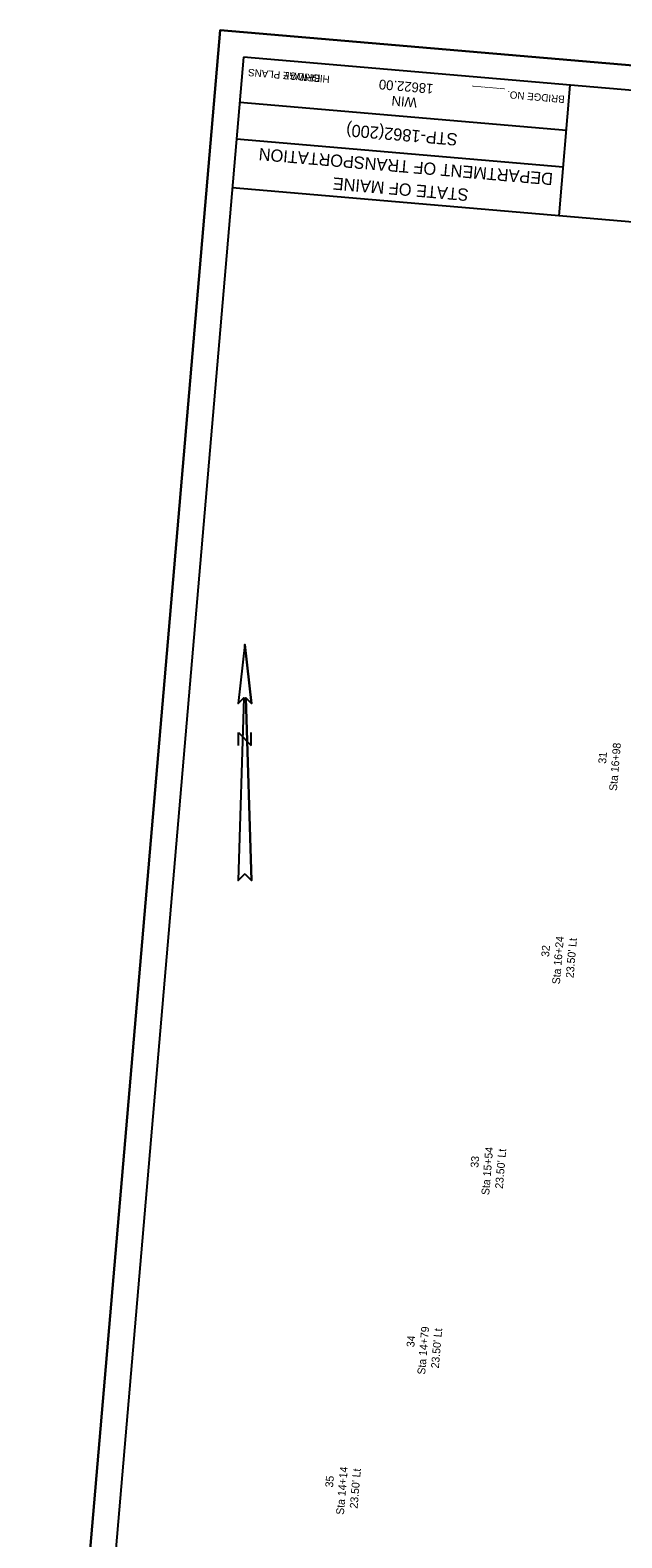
# Model space of a CAD drawing. Extents: x 1137099 to 1137719, y 529062 to 529956.
# Drawn here: x 1137099 to 1137324, y 529381 to 529956 of the extents above; entities that cross this region are included whole.
import ezdxf

# ---------------------------------------------------------------- set-up
doc = ezdxf.new("R2010")
doc.units = 0
for name, color, linetype in [('ANNOTATION', 7, 'Continuous'), ('BORDER', 7, 'Continuous'), ('BRIDGE_TITLE', 7, 'Continuous'), ('D_Lighting_Text', 7, 'Continuous'), ('H_V CONTROLS', 7, 'Continuous'), ('HIGHWAY_TITLE', 7, 'Continuous'), ('PLOT BOUNDARY', 7, 'Continuous')]:
    doc.layers.add(name, color=color, linetype=linetype)

msp = doc.modelspace()

# ---------------------------------------------------------------- linework, layer by layer
at = {"layer": 'ANNOTATION'}
msp.add_lwpolyline([(1137098.65, 529108.8), (1137171.14, 529955.71), (1137719.13, 529908.81), (1137646.65, 529061.9)], close=True, dxfattribs=at)
at = {"layer": 'BORDER'}
for p, q in [((1137179.99, 529945.38), (1137111.77, 529148.3)), ((1137703.07, 529900.61), (1137179.98, 529945.38)), ((1137300.3, 529884.91), (1137304.57, 529934.72)), ((1137303.07, 529917.4), (1137178.53, 529928.06)), ((1137301.88, 529903.48), (1137177.33, 529914.14)), ((1137698.8, 529850.79), (1137175.72, 529895.56))]:
    msp.add_line(p, q, dxfattribs=at)
at = {"layer": 'H_V CONTROLS'}
for p, q in [((1137180.48, 529721.37), (1137177.98, 529698.87)), ((1137180.48, 529721.37), (1137182.98, 529698.87)), ((1137180.1, 529700.99), (1137177.98, 529698.87)), ((1137180.1, 529700.99), (1137177.98, 529631.37)), ((1137180.87, 529700.99), (1137182.98, 529698.87)), ((1137180.87, 529700.99), (1137182.98, 529631.37)), ((1137180.48, 529633.87), (1137177.98, 529631.37)), ((1137180.48, 529633.87), (1137182.98, 529631.37))]:
    msp.add_line(p, q, dxfattribs=at)
for points in [[(1137180.48, 529633.87), (1137182.98, 529631.37), (1137180.87, 529700.99), (1137182.98, 529698.87), (1137180.48, 529721.37), (1137177.98, 529698.87), (1137180.1, 529700.99), (1137177.98, 529631.37), (1137180.48, 529633.87)], [(1137178.12, 529682.87), (1137178.12, 529687.87)], [(1137178.12, 529687.87), (1137182.85, 529682.87)], [(1137182.85, 529682.87), (1137182.85, 529687.87)]]:
    msp.add_lwpolyline(points, dxfattribs=at)
at = {"layer": 'PLOT BOUNDARY'}
msp.add_lwpolyline([(1137646.65, 529061.9), (1137719.13, 529908.81), (1137171.14, 529955.71), (1137098.65, 529108.8)], close=True, dxfattribs=at)

# ---------------------------------------------------------------- texts
at = {"layer": 'BORDER'}
for s, height, p in [('18622.00', 3.726, (1137252.49, 529935.14)), ('WIN', 3.726, (1137246.26, 529929.86)), ('STP-1862(200)', 4.6588, (1137261.77, 529916.26)), ('DEPARTMENT OF TRANSPORTATION', 4.6588, (1137298.12, 529901.18)), ('STATE OF MAINE', 4.6588, (1137265.96, 529895.14))]:
    msp.add_text(s, height=height, rotation=175.10821, dxfattribs=at).set_placement(p)
at = {"layer": 'BRIDGE_TITLE'}
for s, p in [('BRIDGE PLANS', (1137209.4, 529938.64)), ('BRIDGE NO. ______', (1137302.53, 529930.67))]:
    msp.add_text(s, height=2.795, rotation=175.10821, dxfattribs=at).set_placement(p)
at = {"layer": 'D_Lighting_Text'}
for s, p in [('Sta 16+98', (1137322.32, 529665.46)), ('31', (1137318.19, 529675.84)), ('32', (1137296.46, 529602.14)), ('Sta 16+24', (1137300.58, 529591.7)), ("23.50' Lt", (1137305.81, 529594.09)), ('33', (1137269.5, 529521.75)), ('Sta 15+54', (1137273.63, 529511.3)), ("23.50' Lt", (1137278.85, 529513.7)), ('34', (1137245.09, 529453.28)), ('Sta 14+79', (1137249.22, 529442.83)), ("23.50' Lt", (1137254.44, 529445.2)), ('Sta 14+14', (1137218.23, 529389.37)), ("23.50' Lt", (1137223.45, 529391.76)), ('35', (1137214.1, 529399.78))]:
    msp.add_text(s, height=3, rotation=85.10821, dxfattribs=at).set_placement(p)
at = {"layer": 'HIGHWAY_TITLE'}
msp.add_text('HIGHWAY PLANS', height=2.795, rotation=175.10821, dxfattribs=at).set_placement((1137212.94, 529938.34))

doc.saveas('drawing.dxf')
